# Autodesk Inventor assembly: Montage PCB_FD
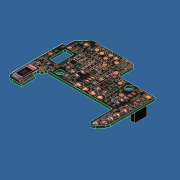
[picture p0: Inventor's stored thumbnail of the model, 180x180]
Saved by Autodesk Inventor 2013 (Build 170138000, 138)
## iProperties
Created: 2011-10
Part Number: Montage PCB_FD
Document SubType Name: Assembly
Designer: Laur
Author: Laur
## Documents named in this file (3)
- D:\_an13-14\FORMULAIRE_2014\Sujet E4 Poissy 2014\Modélisation_7970_shimano_2014\Montage PCB_FD.iam
- D:\_an13-14\FORMULAIRE_2014\Sujet E4 Poissy 2014\Modélisation_7970_shimano_2014\PCB_FD.ipt
- D:\_an13-14\FORMULAIRE_2014\Sujet E4 Poissy 2014\Modélisation_7970_shimano_2014\capteur opto.ipt
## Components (2 placed, 2 different names)
1. PCB_FD:1 — pos capteur / pcb
2. capteur opto:1 — pos capteur / pcb
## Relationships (1: Flush 1)
- pos capteur / pcb [Flush]: PCB_FD:1 ↔ capteur opto:1
